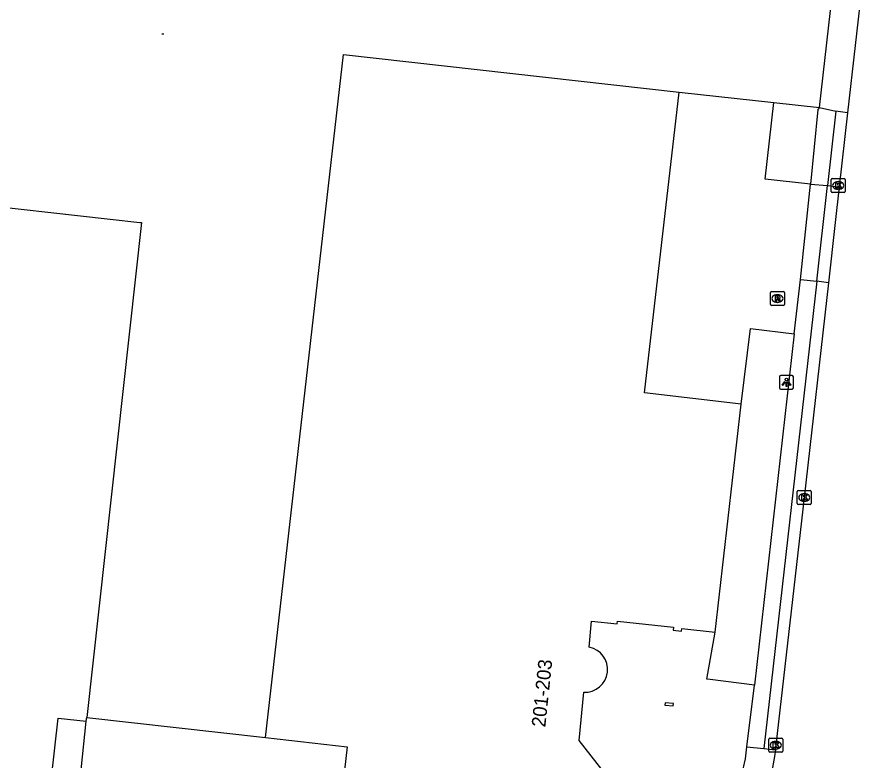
# Model space of a CAD drawing. Extents: x 161389 to 162585, y 388479 to 389761.
# Drawn here: x 162279.1 to 162340.6, y 388693.4 to 388747.2 of the extents above; entities that cross this region are included whole.
import ezdxf

# ---------------------------------------------------------------- set-up
doc = ezdxf.new("R2010")
doc.units = 0
for name, color, linetype in [('IMGEO_Groenvoorziening', 7, 'Continuous'), ('IMGEO_Hek', 7, 'Continuous'), ('IMGEO_Kolk', 7, 'Continuous'), ('IMGEO_Lichtpunt', 7, 'Continuous'), ('IMGEO_Pand', 7, 'Continuous'), ('IMGEO_Pand_nummerreeks', 7, 'Continuous'), ('IMGEO_Parkeervlak_open', 7, 'Continuous'), ('IMGEO_Rijbaan_lokaal_gesloten', 7, 'Continuous'), ('IMGEO_Rijbaan_lokaal_open', 7, 'Continuous'), ('IMGEO_Rioolput', 7, 'Continuous'), ('IMGEO_Voetpad_open', 7, 'Continuous')]:
    doc.layers.add(name, color=color, linetype=linetype)

msp = doc.modelspace()

# ---------------------------------------------------------------- linework, layer by layer
at = {"layer": 'IMGEO_Groenvoorziening'}
msp.add_lwpolyline([(162333.762, 388740.999), (162337.055, 388740.646)], dxfattribs=at)
at = {"layer": 'IMGEO_Hek'}
for points in [[(162289.558, 388745.975), (162289.706, 388745.958)], [(162284.142, 388696.552), (162297.05, 388695.111)]]:
    msp.add_lwpolyline(points, dxfattribs=at)
at = {"layer": 'IMGEO_Kolk'}
for p, q in [((162337.915, 388734.58), (162337.915, 388735.432)), ((162337.99, 388735.506), (162338.842, 388735.506)), ((162338.916, 388735.432), (162338.916, 388734.58)), ((162338.403, 388735.286), (162338.428, 388735.286)), ((162338.842, 388734.506), (162337.99, 388734.506)), ((162338.426, 388734.726), (162338.401, 388734.726)), ((162335.462, 388712.03), (162335.462, 388712.882)), ((162335.537, 388712.956), (162336.389, 388712.956)), ((162335.95, 388712.736), (162335.975, 388712.736)), ((162336.463, 388712.882), (162336.463, 388712.03)), ((162335.973, 388712.176), (162335.948, 388712.176)), ((162336.389, 388711.956), (162335.537, 388711.956)), ((162333.407, 388694.122), (162333.407, 388694.974)), ((162333.482, 388695.048), (162334.334, 388695.048)), ((162333.895, 388694.828), (162333.92, 388694.828)), ((162334.408, 388694.974), (162334.408, 388694.122)), ((162333.918, 388694.268), (162333.893, 388694.268)), ((162334.334, 388694.048), (162333.482, 388694.048))]:
    msp.add_line(p, q, dxfattribs=at)
for points in [[(162337.915, 388734.58), (162337.915, 388735.432)], [(162337.99, 388735.506), (162338.842, 388735.506)], [(162338.916, 388735.432), (162338.916, 388734.58)], [(162338.236, 388735.206), (162338.359, 388735.206), (162338.359, 388735.055), (162338.489, 388735.206), (162338.653, 388735.206), (162338.507, 388735.055), (162338.66, 388734.806), (162338.508, 388734.806), (162338.423, 388734.97), (162338.359, 388734.903), (162338.359, 388734.806), (162338.236, 388734.806), (162338.236, 388735.206)], [(162338.842, 388734.506), (162337.99, 388734.506)], [(162335.462, 388712.03), (162335.462, 388712.882)], [(162335.537, 388712.956), (162336.389, 388712.956)], [(162335.783, 388712.656), (162335.906, 388712.656), (162335.906, 388712.505), (162336.036, 388712.656), (162336.2, 388712.656), (162336.054, 388712.505), (162336.207, 388712.256), (162336.055, 388712.256), (162335.97, 388712.42), (162335.906, 388712.353), (162335.906, 388712.256), (162335.783, 388712.256), (162335.783, 388712.656)], [(162336.463, 388712.882), (162336.463, 388712.03)], [(162336.389, 388711.956), (162335.537, 388711.956)], [(162333.407, 388694.122), (162333.407, 388694.974)], [(162333.482, 388695.048), (162334.334, 388695.048)], [(162334.408, 388694.974), (162334.408, 388694.122)], [(162333.728, 388694.748), (162333.851, 388694.748), (162333.851, 388694.597), (162333.981, 388694.748), (162334.145, 388694.748), (162333.999, 388694.597), (162334.152, 388694.348), (162334, 388694.348), (162333.915, 388694.512), (162333.851, 388694.445), (162333.851, 388694.348), (162333.728, 388694.348), (162333.728, 388694.748)], [(162334.334, 388694.048), (162333.482, 388694.048)]]:
    msp.add_lwpolyline(points, dxfattribs=at)
for centre, start, end in [((162337.992, 388735.43), 91.55205, 178.44795), ((162337.992, 388735.43), 91.55205, 178.44795), ((162338.84, 388735.43), 1.55205, 88.44795), ((162338.84, 388735.43), 1.55205, 88.44795), ((162337.992, 388734.582), 181.55205, 268.44795), ((162337.992, 388734.582), 181.55205, 268.44795), ((162338.84, 388734.582), 271.55205, 358.44795), ((162338.84, 388734.582), 271.55205, 358.44795), ((162335.539, 388712.88), 91.55205, 178.44795), ((162335.539, 388712.88), 91.55205, 178.44795), ((162336.387, 388712.88), 1.55205, 88.44795), ((162336.387, 388712.88), 1.55205, 88.44795), ((162335.539, 388712.032), 181.55205, 268.44795), ((162335.539, 388712.032), 181.55205, 268.44795), ((162336.387, 388712.032), 271.55205, 358.44795), ((162336.387, 388712.032), 271.55205, 358.44795), ((162333.484, 388694.972), 91.55205, 178.44795), ((162333.484, 388694.972), 91.55205, 178.44795), ((162334.332, 388694.972), 1.55205, 88.44795), ((162334.332, 388694.972), 1.55205, 88.44795), ((162333.484, 388694.124), 181.55205, 268.44795), ((162333.484, 388694.124), 181.55205, 268.44795), ((162334.332, 388694.124), 271.55205, 358.44795), ((162334.332, 388694.124), 271.55205, 358.44795)]:
    msp.add_arc(centre, 0.0765, start, end, dxfattribs=at)
for centre, major_axis, ratio, start_param, end_param in [((162338.402, 388735.006), (-0.387, 0.002), 0.722429, 4.712389, 7.853982), ((162338.427, 388735.006), (-0.39, 0.002), 0.717154, 1.570796, 4.712389), ((162335.949, 388712.456), (-0.387, 0.002), 0.722429, 4.712389, 7.853982), ((162335.974, 388712.456), (-0.39, 0.002), 0.717154, 1.570796, 4.712389), ((162333.894, 388694.548), (-0.387, 0.002), 0.722429, 4.712389, 7.853982), ((162333.919, 388694.548), (-0.39, 0.002), 0.717154, 1.570796, 4.712389)]:
    msp.add_ellipse(centre, major_axis=major_axis, ratio=ratio, start_param=start_param, end_param=end_param, dxfattribs=at)
at = {"layer": 'IMGEO_Lichtpunt'}
for p, q in [((162335.081, 388721.27), (162334.273, 388721.27)), ((162335.081, 388721.27), (162334.273, 388721.27)), ((162334.179, 388721.175), (162334.179, 388720.368)), ((162334.179, 388721.175), (162334.179, 388720.368)), ((162335.175, 388720.368), (162335.175, 388721.175)), ((162335.175, 388720.368), (162335.175, 388721.175)), ((162334.273, 388720.274), (162335.081, 388720.274)), ((162334.273, 388720.274), (162335.081, 388720.274))]:
    msp.add_line(p, q, dxfattribs=at)
for points in [[(162334.553, 388720.839), (162334.592, 388720.811), (162334.404, 388720.549), (162334.366, 388720.576), (162334.553, 388720.839)], [(162334.655, 388720.791), (162334.702, 388720.791), (162334.702, 388720.469), (162334.655, 388720.469), (162334.655, 388720.791)], [(162334.765, 388720.811), (162334.803, 388720.838), (162334.99, 388720.576), (162334.951, 388720.548), (162334.765, 388720.811)]]:
    msp.add_lwpolyline(points, dxfattribs=at)
msp.add_circle((162334.678, 388720.973), 0.0994, dxfattribs=at)
for centre, start, end in [((162334.273, 388721.175), 90, 180), ((162334.273, 388721.175), 90, 180), ((162335.081, 388721.175), 0, 90), ((162335.081, 388721.175), 0, 90), ((162334.273, 388720.368), 180, 270), ((162334.273, 388720.368), 180, 270), ((162335.081, 388720.368), 270, 0), ((162335.081, 388720.368), 270, 360)]:
    msp.add_arc(centre, 0.0946, start, end, dxfattribs=at)
at = {"layer": 'IMGEO_Pand'}
for points in [[(162297.05, 388695.111), (162302.682, 388744.476), (162326.936, 388741.737)], [(162331.4, 388719.2), (162324.434, 388720.007), (162326.936, 388741.737)], [(162266.146, 388697.835), (162266.198, 388698.415), (162268.938, 388698.17), (162272.942, 388734.017), (162287.984, 388732.337), (162288.104, 388732.324), (162284.142, 388696.552)], [(162329.52, 388702.715), (162331.4, 388719.2)], [(162320.426, 388701.628), (162320.597, 388703.524), (162322.446, 388703.319), (162322.477, 388703.517), (162326.528, 388703.072), (162326.504, 388702.873), (162327.103, 388702.801), (162327.121, 388702.995), (162329.52, 388702.715)], [(162325.071, 388688.022), (162319.695, 388694.883), (162320.038, 388698.378)], [(162266.146, 388697.835), (162265.455, 388691.401), (162281.314, 388689.643), (162282.073, 388696.501), (162284.111, 388696.275)], [(162326.503, 388697.397), (162326.516, 388697.575), (162325.914, 388697.616), (162325.902, 388697.438), (162326.503, 388697.397)], [(162284.111, 388696.275), (162284.142, 388696.552)], [(162297.05, 388695.111), (162302.955, 388694.443), (162302.151, 388687.471)]]:
    msp.add_lwpolyline(points, dxfattribs=at)
msp.add_arc((162320.127, 388700.016), 1.64, 266.90285, 79.48113, dxfattribs=at)
at = {"layer": 'IMGEO_Parkeervlak_open'}
for points in [[(162326.936, 388741.737), (162333.762, 388740.999)], [(162336.423, 388735.109), (162333.138, 388735.461), (162333.762, 388740.999)], [(162331.4, 388719.2), (162332.085, 388724.677), (162335.236, 388724.284)]]:
    msp.add_lwpolyline(points, dxfattribs=at)
at = {"layer": 'IMGEO_Rijbaan_lokaal_gesloten'}
for points in [[(162340.637, 388753.967), (162340.189, 388750), (162339.087, 388740.255)], [(162339.087, 388740.255), (162338.482, 388734.9)], [(162338.482, 388734.9), (162338.192, 388732.338), (162337.703, 388727.976)], [(162337.703, 388727.976), (162335.964, 388712.455), (162333.91, 388694.548), (162333.881, 388694.226)], [(162333.881, 388694.226), (162333.824, 388693.74), (162333.584, 388692.406), (162333.226, 388691.098), (162332.752, 388689.827), (162332.167, 388688.604), (162331.474, 388687.438), (162330.681, 388686.339), (162329.792, 388685.315), (162328.816, 388684.374), (162327.759, 388683.524), (162326.631, 388682.772), (162325.44, 388682.124), (162324.195, 388681.585), (162322.908, 388681.159), (162321.588, 388680.85), (162320.245, 388680.66), (162318.891, 388680.591), (162317.536, 388680.643)]]:
    msp.add_lwpolyline(points, dxfattribs=at)
at = {"layer": 'IMGEO_Rijbaan_lokaal_open'}
for points in [[(162283.731, 388692.772), (162284.111, 388696.275)], [(162284.142, 388696.552), (162297.05, 388695.111)]]:
    msp.add_lwpolyline(points, dxfattribs=at)
at = {"layer": 'IMGEO_Rioolput'}
for p, q in [((162333.527, 388726.405), (162333.527, 388727.257)), ((162333.602, 388727.331), (162334.454, 388727.331)), ((162334.015, 388727.111), (162334.04, 388727.111)), ((162334.528, 388727.257), (162334.528, 388726.405)), ((162334.454, 388726.331), (162333.602, 388726.331)), ((162334.038, 388726.551), (162334.013, 388726.551))]:
    msp.add_line(p, q, dxfattribs=at)
for points in [[(162333.527, 388726.405), (162333.527, 388727.257)], [(162333.602, 388727.331), (162334.454, 388727.331)], [(162334.116, 388727.029), (162333.864, 388727.031), (162333.864, 388726.631)], [(162333.864, 388726.631), (162333.988, 388726.631), (162333.988, 388726.793), (162333.999, 388726.793)], [(162334.042, 388726.95), (162333.988, 388726.95), (162333.988, 388726.869)], [(162333.988, 388726.869), (162334.04, 388726.869)], [(162334.528, 388727.257), (162334.528, 388726.405)], [(162334.454, 388726.331), (162333.602, 388726.331)], [(162334.046, 388726.764), (162334.117, 388726.631), (162334.257, 388726.631), (162334.192, 388726.757)]]:
    msp.add_lwpolyline(points, dxfattribs=at)
for centre, radius, start, end in [((162333.604, 388727.255), 0.0765, 91.55205, 178.44795), ((162333.604, 388727.255), 0.0765, 91.55205, 178.44795), ((162333.998, 388726.74), 0.0533, 26.02933, 88.69889), ((162334.024, 388727.058), 0.19, 274.7715, 282.96867), ((162334.048, 388726.854), 0.0964, 77.00612, 93.18647), ((162334.062, 388726.911), 0.0378, 276.66336, 79.67722), ((162334.115, 388726.919), 0.109, 350.36119, 89.41601), ((162334.113, 388726.919), 0.112, 277.58423, 350.98172), ((162334.097, 388726.704), 0.108, 29.51342, 73.79051), ((162334.452, 388727.255), 0.0765, 1.55205, 88.44795), ((162334.452, 388727.255), 0.0765, 1.55205, 88.44795), ((162333.604, 388726.407), 0.0765, 181.55205, 268.44795), ((162333.604, 388726.407), 0.0765, 181.55205, 268.44795), ((162334.452, 388726.407), 0.0765, 271.55205, 358.44795), ((162334.452, 388726.407), 0.0765, 271.55205, 358.44795)]:
    msp.add_arc(centre, radius, start, end, dxfattribs=at)
for centre, major_axis, ratio, start_param, end_param in [((162334.014, 388726.831), (-0.387, 0.002), 0.722429, 4.712389, 7.853982), ((162334.039, 388726.831), (-0.39, 0.002), 0.717154, 1.570796, 4.712389)]:
    msp.add_ellipse(centre, major_axis=major_axis, ratio=ratio, start_param=start_param, end_param=end_param, dxfattribs=at)
at = {"layer": 'IMGEO_Voetpad_open'}
for points in [[(162337.055, 388740.646), (162338.13, 388750), (162338.455, 388752.823)], [(162337.055, 388740.646), (162336.951, 388740.497), (162336.423, 388735.109)], [(162337.055, 388740.646), (162338.244, 388740.364)], [(162338.244, 388740.364), (162337.644, 388735.007)], [(162339.087, 388740.255), (162338.244, 388740.364)], [(162335.69, 388728.208), (162336.423, 388735.109)], [(162336.423, 388735.109), (162337.644, 388735.007)], [(162336.869, 388728.082), (162337.644, 388735.007)], [(162337.644, 388735.007), (162338.482, 388734.9)], [(162336.869, 388728.082), (162333.048, 388694.31)], [(162335.236, 388724.284), (162335.69, 388728.208)], [(162335.69, 388728.208), (162336.869, 388728.082)], [(162337.703, 388727.976), (162336.869, 388728.082)], [(162335.236, 388724.284), (162332.361, 388698.894)], [(162332.361, 388698.894), (162329.17, 388699.288), (162328.939, 388699.317), (162329.52, 388702.715)], [(162331.828, 388694.434), (162332.361, 388698.894)], [(162327.076, 388685.556), (162327.953, 388686.345), (162328.757, 388687.21), (162329.48, 388688.143), (162330.116, 388689.137), (162330.661, 388690.183), (162331.111, 388691.274), (162331.462, 388692.401), (162331.71, 388693.555), (162331.828, 388694.434)], [(162331.828, 388694.434), (162333.048, 388694.31)], [(162333.048, 388694.31), (162333.881, 388694.226)]]:
    msp.add_lwpolyline(points, dxfattribs=at)

# ---------------------------------------------------------------- texts
at = {"layer": 'IMGEO_Pand_nummerreeks'}
msp.add_text('201-203', height=1, rotation=84.0407, dxfattribs=at).set_placement((162317.259, 388695.818))

doc.saveas('drawing.dxf')
